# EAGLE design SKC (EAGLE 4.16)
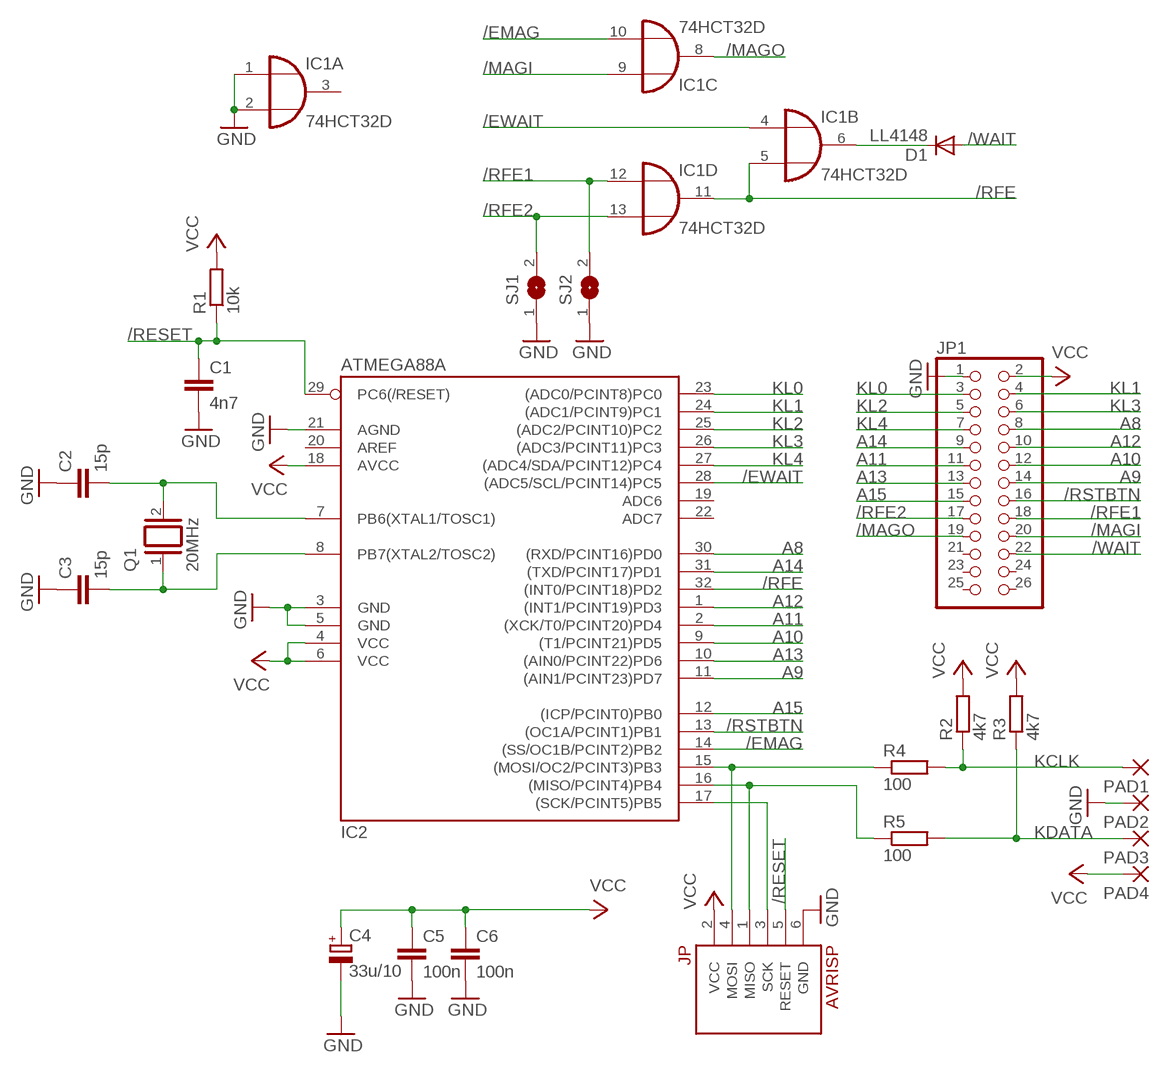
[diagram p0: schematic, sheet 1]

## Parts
C1  4n7  C-EUC0805  [C0805]
C2  15p  C-EUC0805  [C0805]
C3  15p  C-EUC0805  [C0805]
C4  33u/10  CPOL-EUSMCD  [SMC_D]
C5  100n  C-EUC0805  [C0805]
C6  100n  C-EUC0805  [C0805]
D1  LL4148  DIODE-MINIMELF  [MINIMELF]
IC1  74HCT32D  [SO14]
IC2  ATMEGA88A  [TQFP32]
JP  AVRISP  [2X3]
JP1  PINHD-2X13  [2X13]
PAD1  2,54/1,0  [2,54/1,0]
PAD2  2,54/1,0  [2,54/1,0]
PAD3  2,54/1,0  [2,54/1,0]
PAD4  2,54/1,0  [2,54/1,0]
Q1  20MHz  XTAL/S  [QS]
R1  10k  R-EU_R0805  [R0805]
R2  4k7  R-EU_R0805  [R0805]
R3  4k7  R-EU_R0805  [R0805]
R4  100  R-EU_R0805  [R0805]
R5  100  R-EU_R0805  [R0805]
SJ1  SJ  [SJ]
SJ2  SJ  [SJ]

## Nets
/EMAG: IC1.10(C:I1) IC2.14((SS/OC1B/PCINT2)PB2)
/EWAIT: IC1.4(B:I0) IC2.28((ADC5/SCL/PCINT14)PC5)
/MAGI: IC1.9(C:I0) JP1.20
/MAGO: IC1.8(C:O) JP1.19
/RESET: C1.1 IC2.29(PC6(/RESET)) JP.5(RESET) R1.1
/RFE: IC1.5(B:I1) IC1.11(D:O) IC2.32((INT0/PCINT18)PD2)
/RFE1: IC1.12(D:I0) JP1.18 SJ2.2
/RFE2: IC1.13(D:I1) JP1.17 SJ1.2
/RSTBTN: IC2.13((OC1A/PCINT1)PB1) JP1.16
/WAIT: D1.A JP1.22
A8: IC2.30((RXD/PCINT16)PD0) JP1.8
A9: IC2.11((AIN1/PCINT23)PD7) JP1.14
A10: IC2.9((T1/PCINT21)PD5) JP1.12
A11: IC2.2((XCK/T0/PCINT20)PD4) JP1.11
A12: IC2.1((INT1/PCINT19)PD3) JP1.10
A13: IC2.10((AIN0/PCINT22)PD6) JP1.13
A14: IC2.31((TXD/PCINT17)PD1) JP1.9
A15: IC2.12((ICP/PCINT0)PB0) JP1.15
GND: C1.2 C2.1 C3.1 C4.- C5.2 C6.2 IC1.1(A:I0) IC1.2(A:I1) IC2.3(GND) IC2.5(GND) IC2.21(AGND) JP1.1 JP.6(GND) PAD2.1(P) SJ1.1 SJ2.1
KCLK: PAD1.1(P) R2.1 R4.2
KDATA: PAD3.1(P) R3.1 R5.2
KL0: IC2.23((ADC0/PCINT8)PC0) JP1.3
KL1: IC2.24((ADC1/PCINT9)PC1) JP1.4
KL2: IC2.25((ADC2/PCINT10)PC2) JP1.5
KL3: IC2.26((ADC3/PCINT11)PC3) JP1.6
KL4: IC2.27((ADC4/SDA/PCINT12)PC4) JP1.7
N$1: C3.2 IC2.8(PB7(XTAL2/TOSC2)) Q1.1
N$2: C2.2 IC2.7(PB6(XTAL1/TOSC1)) Q1.2
N$3: IC2.15((MOSI/OC2/PCINT3)PB3) JP.4(MOSI) R4.1
N$4: IC2.16((MISO/PCINT4)PB4) JP.1(MISO) R5.1
N$5: IC2.17((SCK/PCINT5)PB5) JP.3(SCK)
N$7: D1.C IC1.6(B:O)
VCC: C4.+ C5.1 C6.1 IC2.4(VCC) IC2.6(VCC) IC2.18(AVCC) JP1.2 JP.2(VCC) PAD4.1(P) R1.2 R2.2 R3.2
Unconnected: IC1.3(A:O) IC2.19(ADC6) IC2.20(AREF) IC2.22(ADC7) JP1.21 JP1.23 JP1.24 JP1.25 JP1.26

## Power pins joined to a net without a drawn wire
GND: IC1.7(P:GND)
VCC: IC1.14(P:VCC)

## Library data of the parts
C1-C3 C5 C6 = rcl:C-EU: CAPACITOR, European symbol
C4 = rcl:CPOL-EU: POLARIZED CAPACITOR, European symbol
D1 = diode:DIODE-: DIODE
IC1 = 74xx-eu:74*32: Quad 2-input OR gate
IC2 = atmega88:ATMEGA88*A
JP = avrprog:AVRISP
JP1 = pinhead:PINHD-2X13: PIN HEADER
PAD1-PAD4 = wirepad:2,54/1,0: THROUGH-HOLE PAD
Q1 = special:XTAL/S: CRYSTAL
R1-R5 = rcl:R-EU_: RESISTOR, European symbol
SJ1 SJ2 = jumper:SJ: SMD solder JUMPER

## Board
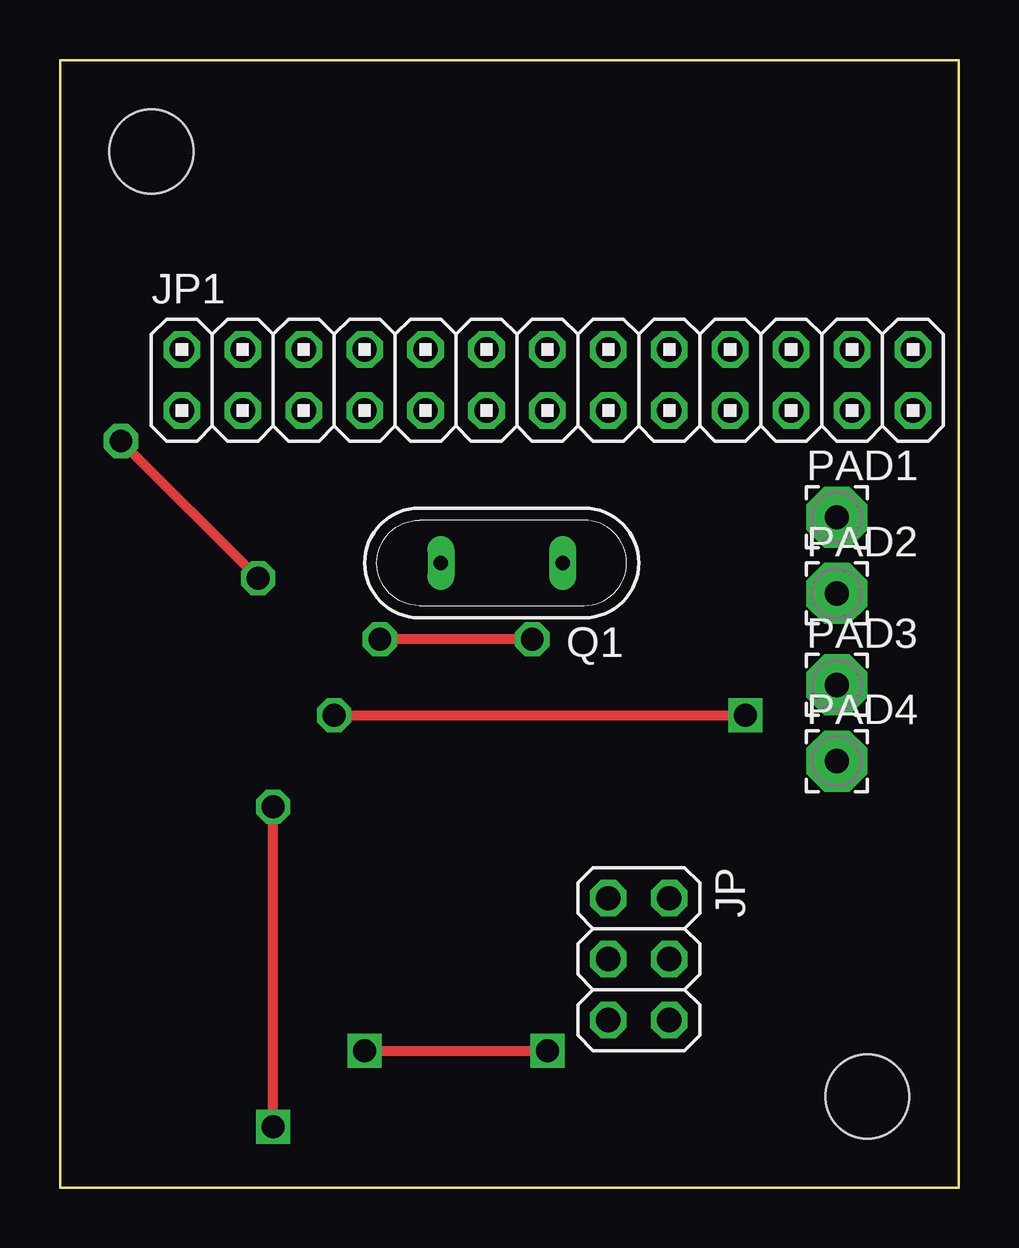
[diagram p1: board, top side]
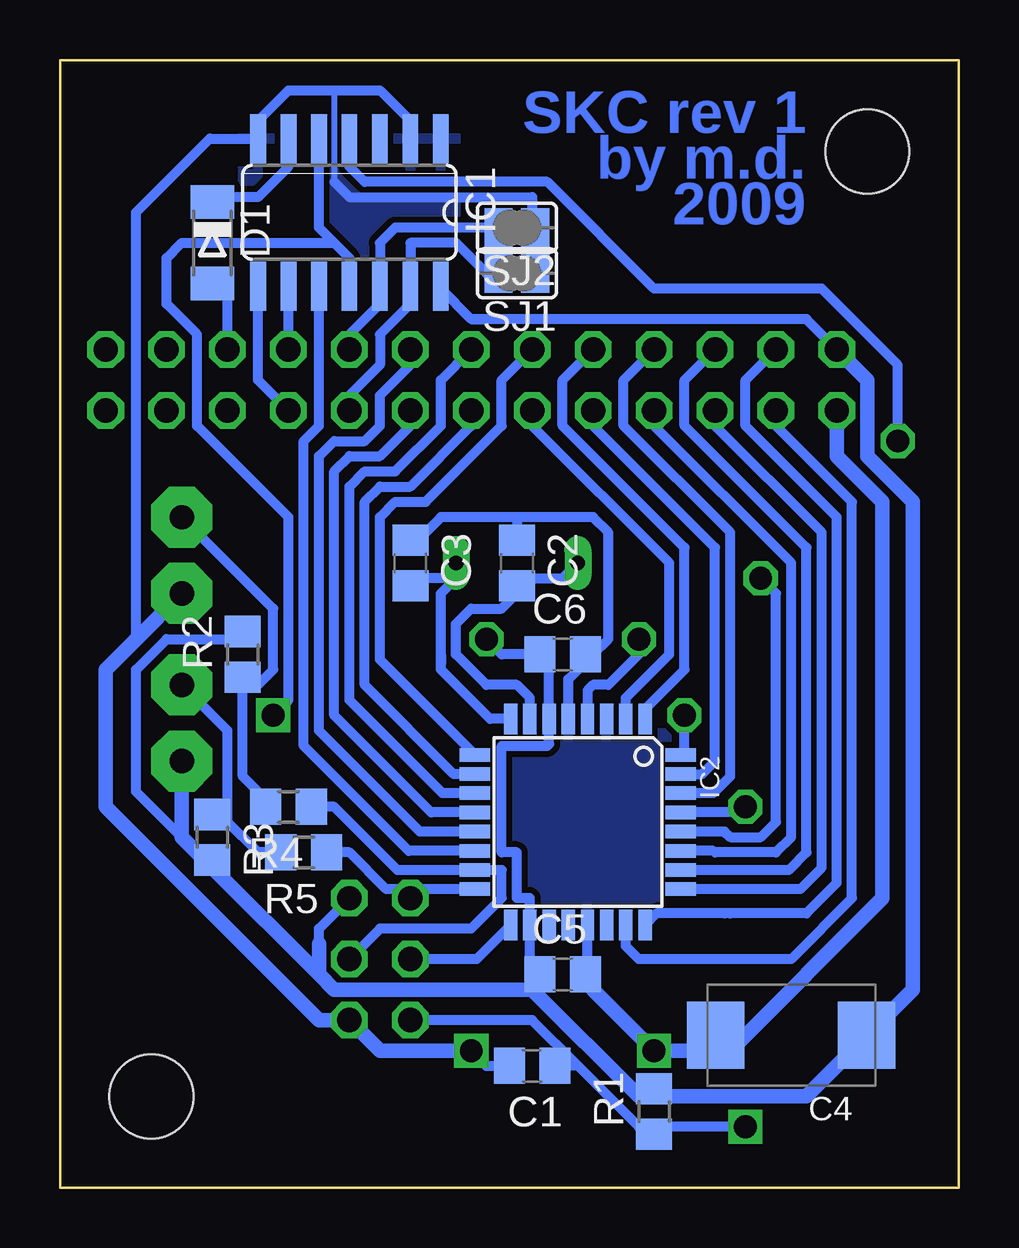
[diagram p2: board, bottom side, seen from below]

Size 37.47 x 46.99 mm. Coordinates in mm from the lower left corner, seen from the top.
Outline: 0,0 0,46.99 37.47,46.99 37.47,0 0,0
Copper layers (1*16): Top 0.035mm / dielectric 1.5mm / Bottom 0.035mm
Design rules "default": minimum track width 10mil, minimum drill 24mil, track to track 8mil, track to pad 7mil, pad to pad 8mil, via to via 8mil, smd to smd 8mil, copper to edge 40mil, drill to drill 8mil, minimum pad ring 10mil, minimum via ring 8mil, stop-mask expansion 4mil, vias tented up to drill 0mil, thermal gap 10mil
Holes 3.5 mm at 33.66,3.81 3.81,43.18

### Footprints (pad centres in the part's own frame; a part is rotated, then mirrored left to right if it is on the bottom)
C0805 = smd 1.3 x 1.5: 1 -0.95,0; 2 0.95,0
SMC_D = smd 2.4 x 2.8: + -3.15,0; - 3.15,0
MINIMELF = smd 1.4 x 1.8: A 1.7,0; C -1.7,0
SO14 = smd 0.66 x 2.032: 1 -3.81,-3.073; 2 -2.54,-3.073; 3 -1.27,-3.073; 4 0,-3.073; 5 1.27,-3.073; 6 2.54,-3.073; 7 3.81,-3.073; 8 3.81,3.073; 9 2.54,3.073; 10 1.27,3.073; 11 0,3.073; 12 -1.27,3.073; 13 -2.54,3.073; 14 -3.81,3.073
TQFP32 = smd 1.27 x 0.559: 1 -4.293,2.8; 2 -4.293,2; 3 -4.293,1.2; 4 -4.293,0.4; 5 -4.293,-0.4; 6 -4.293,-1.2; 7 -4.293,-2; 8 -4.293,-2.8; 17 4.293,-2.8; 18 4.293,-2; 19 4.293,-1.2; 20 4.293,-0.4; 21 4.293,0.4; 22 4.293,1.2; 23 4.293,2; 24 4.293,2.8 | smd 0.559 x 1.27: 9 -2.8,-4.293; 10 -2,-4.293; 11 -1.2,-4.293; 12 -0.4,-4.293; 13 0.4,-4.293; 14 1.2,-4.293; 15 2,-4.293; 16 2.8,-4.293; 25 2.8,4.293; 26 2,4.293; 27 1.2,4.293; 28 0.4,4.293; 29 -0.4,4.293; 30 -1.2,4.293; 31 -2,4.293; 32 -2.8,4.293
2X3 = drill 1.016 octagon: 1 -2.54,-1.27; 2 -2.54,1.27; 3 0,-1.27; 4 0,1.27; 5 2.54,-1.27; 6 2.54,1.27
2X13 = drill 1.016 octagon: 1 -15.24,-1.27; 2 -15.24,1.27; 3 -12.7,-1.27; 4 -12.7,1.27; 5 -10.16,-1.27; 6 -10.16,1.27; 7 -7.62,-1.27; 8 -7.62,1.27; 9 -5.08,-1.27; 10 -5.08,1.27; 11 -2.54,-1.27; 12 -2.54,1.27; 13 0,-1.27; 14 0,1.27; 15 2.54,-1.27; 16 2.54,1.27; 17 5.08,-1.27; 18 5.08,1.27; 19 7.62,-1.27; 20 7.62,1.27; 21 10.16,-1.27; 22 10.16,1.27; 23 12.7,-1.27; 24 12.7,1.27; 25 15.24,-1.27; 26 15.24,1.27
2,54/1,0 = drill 1.016 pad 2.54 octagon: 1 0,0
QS = drill 0.61 long: 1 -2.54,0; 2 2.54,0
R0805 = smd 1.3 x 1.5: 1 -0.95,0; 2 0.95,0
SJ = smd 1.168 x 1.6: 1 -0.762,0; 2 0.762,0

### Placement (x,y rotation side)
C1  17.78,5.08 180 bottom
C2  18.41,26.04 270 bottom
C3  22.86,26.04 270 bottom
C4  6.99,6.35 180 bottom
C5  16.51,8.89 0 bottom
C6  16.51,22.23 0 bottom
D1  31.11,39.37 270 bottom
IC1  25.4,40.64 180 bottom
IC2  15.88,15.24 270 bottom
JP  24.13,9.53 270 top
JP1  20.32,33.66 0 top
PAD1  32.38,27.94 0 top
PAD2  32.38,24.77 0 top
PAD3  32.38,20.95 0 top
PAD4  32.38,17.78 0 top
Q1  18.41,26.04 180 top
R1  12.7,3.17 90 bottom
R2  29.84,22.23 90 bottom
R3  31.11,14.61 270 bottom
R4  27.94,15.88 180 bottom
R5  27.3,13.97 180 bottom
SJ1  18.41,38.1 180 bottom
SJ2  18.41,40.01 180 bottom

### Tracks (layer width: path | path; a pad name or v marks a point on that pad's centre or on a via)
/EMAG
  Bottom 0.406: IC2.14 22.93,14.04 27.3,18.41 27.3,31.11 26.67,31.75 IC1.10
/EWAIT  (via drill 0.95)
  Top 0.406: v8.26,25.4 v2.54,31.11
  Bottom 0.406: IC2.28 9.76,14.84 9.53,14.61 8.26,14.61 7.62,15.24 7.62,24.77 v8.26,25.4 | v2.54,31.11 2.54,34.29 5.71,37.47 12.7,37.47 17.14,41.91 24.77,41.91 25.4,42.55 25.4,43.81 IC1.4
/MAGI
  Bottom 0.406: JP1.20 IC1.9
/MAGO
  Bottom 0.406: IC1.8 29.21,33.66 JP1.19
/RESET  (via drill 0.95)
  Top 0.406: v8.89,2.54 v8.89,15.88
  Bottom 0.254: 12.7,2.54 R1.1
  Bottom 0.406: IC2.29 9.12,15.64 v8.89,15.88 | JP.5 17.78,6.99 15.88,5.08 | 15.88,5.08 13.34,2.54 12.7,2.54 v8.89,2.54 | 15.88,5.08 C1.1
/RFE  (via drill 0.95)
  Top 0.406: v11.43,19.68 v28.57,19.68
  Bottom 0.406: IC2.32 11.43,18.19 v11.43,19.68 | v28.57,19.68 27.94,20.32 27.94,27.94 31.75,31.75 31.75,35.56 33.02,36.83 33.02,38.73 32.38,39.37 26.04,39.37 | IC1.11 25.4,38.73 26.04,39.37 | 26.04,39.37 26.67,40.01 IC1.5 26.67,43.81
/RFE1
  Bottom 0.406: JP1.18 25.4,35.56 24.13,36.83 IC1.12 24.13,39.37 23.5,40.01 SJ2.2 19.05,40.01
/RFE2
  Bottom 0.406: JP1.17 25.4,33.02 24.13,34.29 24.13,35.56 22.86,36.83 IC1.13 22.86,39.37 20.95,39.37 19.68,38.1 SJ1.2 19.05,38.1
/RSTBTN
  Bottom 0.406: IC2.13 22.46,14.84 26.67,19.05 26.67,30.48 26.04,31.11 24.77,31.11 24.13,31.75 24.13,33.02 22.86,34.29 JP1.16
/WAIT
  Bottom 0.406: D1.A 31.11,37.47 30.48,37.47 JP1.22
A8
  Bottom 0.406: IC2.30 10.23,16.44 9.53,17.14 9.53,27.3 13.97,31.75 13.97,33.66 JP1.8
A9
  Bottom 0.406: IC2.11 21.52,16.44 25.4,20.32 25.4,29.21 24.77,29.84 23.5,29.84 21.59,31.75 21.59,33.66 JP1.14
A10
  Bottom 0.406: IC2.9 24.13,22 24.13,27.94 23.5,28.57 22.23,28.57 19.05,31.75 19.05,33.66 JP1.12
A11
  Bottom 0.406: IC2.2 13.88,20.41 12.06,22.23 12.06,26.04 17.78,31.75 JP1.11
A12
  Bottom 0.406: IC2.1 13.07,19.95 11.43,21.59 11.43,26.67 16.51,31.75 16.51,33.66 JP1.10
A13
  Bottom 0.406: IC2.10 21.05,17.24 24.77,20.95 24.77,28.57 24.13,29.21 22.86,29.21 20.32,31.75 JP1.13
A14
  Bottom 0.406: IC2.31 10.7,17.24 10.16,17.78 10.16,26.67 15.24,31.75 JP1.9
A15
  Bottom 0.406: IC2.12 21.99,15.64 26.04,19.68 26.04,29.84 25.4,30.48 24.13,30.48 22.86,31.75 JP1.15
GND  (via drill 0.95)
  Top 0.406: v12.7,5.71 v20.32,5.71
  Bottom 0.254: 26.04,45.72 26.04,41.91
  Bottom 0.406: 18.41,27.94 C2.1 | C3.1 22.55,26.98 21.59,27.94 18.41,27.94 | IC2.5 16.27,21.19 15.24,22.23 | 15.24,22.23 14.61,22.86 14.61,27.3 15.24,27.94 18.41,27.94 | 15.47,9.12 IC2.21 | v20.32,5.71 19.68,5.08 C1.2 | 15.88,22.23 C6.2 15.24,22.23 | C4.- 10.16,6.35 10.16,5.71 9.53,5.71 | 34.29,22.86 34.29,40.64 31.22,43.71 IC1.7 29.21,44.45 27.94,45.72 26.04,45.72 24.13,45.72 22.86,44.45 IC1.2 | 26.04,41.91 25.4,41.27 17.78,41.27 17.78,40.01 | SJ1.1 17.78,38.1 17.78,40.01 | 17.78,40.01 SJ2.1 | IC1.1 21.59,44.45
  Bottom 0.61: v20.32,5.71 24.13,5.71 JP.6 26.67,6.99 35.56,15.88 35.56,21.59 34.29,22.86 PAD2.1 | 10.16,5.71 v12.7,5.71 15.24,8.26 15.24,8.89 | 15.24,8.89 15.47,9.12 | 15.24,8.89 C5.2 | JP1.1 5.08,30.48 3.17,28.57 3.17,12.06 9.53,5.71
  pour Bottom (isolate 0.254): 12.06,11.43 12.06,19.05 19.68,19.05 19.68,11.43
  pour Bottom (isolate 0.254): 20.95,36.83 20.95,44.45 29.84,44.45 29.84,36.83
KCLK
  Bottom 0.406: 29.21,15.88 28.89,16.2 R4.2 29.21,15.88 | 29.21,15.88 29.21,16.51 29.84,17.14 29.84,20.95 | 29.84,20.95 R2.1 | 29.84,20.95 29.21,20.95 28.57,21.59 28.57,24.13 PAD1.1
KDATA
  Bottom 0.406: R5.2 29.21,13.97 30.48,15.24 | 30.48,15.24 30.48,19.05 PAD3.1 | 30.48,15.24 31.11,15.24 R3.1
KL0
  Bottom 0.406: IC2.23 13.88,10.06 13.34,9.53 6.99,9.53 4.45,12.06 4.45,28.57 7.62,31.75 JP1.3
KL1
  Bottom 0.406: 9.53,11.43 9.75,11.43 | 9.53,11.43 6.35,11.43 5.08,12.7 5.08,27.94 8.89,31.75 8.89,33.66 JP1.4 | IC2.24 12.59,11.43 9.53,11.43
KL2
  Bottom 0.406: IC2.25 6.61,12.44 5.71,13.34 5.71,27.3 10.16,31.75 JP1.5
KL3
  Bottom 0.406: IC2.26 7.08,13.24 6.35,13.97 6.35,26.67 11.43,31.75 11.43,33.66 JP1.6
KL4
  Bottom 0.406: IC2.27 10.23,14.04 10.16,13.97 7.62,13.97 6.99,14.61 6.99,26.04 12.7,31.75 JP1.7
N$1
  Bottom 0.406: 21.59,22.23 21.59,21.81 | 21.59,22.23 21.59,21.59 19.53,19.53 IC2.8 | 20.95,25.4 Q1.1 | 20.95,25.4 21.59,24.77 21.59,22.23 | C3.2 22.55,25.4 20.95,25.4
N$2
  Bottom 0.406: IC2.7 17.88,20.41 18.41,20.95 19.68,20.95 20.95,22.23 20.95,23.5 20.32,24.13 19.05,24.13 18.41,24.77 18.41,25.4 | 18.41,25.4 C2.2 | Q1.2 16.51,25.4 18.41,25.4
N$3
  Bottom 0.406: JP.4 24.13,10.79 20.32,10.79 19.05,12.06 19.05,13.24 IC2.15 23.4,13.24 26.04,15.88 R4.1
N$4
  Bottom 0.406: 22.48,12.44 JP.1 | IC2.16 22.48,12.44 | R5.1 25.4,13.97 23.87,12.44 22.48,12.44
N$5
  Bottom 0.406: IC2.17 20.1,9.53 JP.3
N$7
  Bottom 0.406: IC1.6 27.94,42.55 29.21,41.27 31.11,41.27 D1.C
VCC  (via drill 0.95)
  Top 0.406: v19.68,22.86 v13.34,22.86
  Bottom 0.254: 12.7,3.81 R1.2
  Bottom 0.406: JP.2 26.67,10.79 26.67,10.16 | 17.78,8.89 17.88,8.98 IC2.18 17.88,12.06 18.41,12.06 18.41,13.97 19.05,13.97 19.05,18.41 17.14,18.41 17.07,18.48 IC2.6 17.07,22.3 17.14,22.23 C6.1 19.05,22.23 v19.68,22.86 | IC2.4 15.47,20.72 15.24,20.95 14.61,20.95 13.34,22.23 v13.34,22.86 | C4.+ 3.81,6.35 | 20.32,36.2 6.35,36.2 JP1.2 | 20.32,36.2 19.68,36.2 | 20.32,36.2 21.59,37.47 | 21.59,37.47 21.59,36.83 | 21.59,37.47 IC1.14 | R2.2 29.84,22.86 33.02,22.86 34.29,21.59 34.29,16.51 32.38,14.61 | 31.11,13.34 R3.2
  Bottom 0.61: 26.67,8.89 26.67,10.16 | 26.67,8.89 26.04,8.26 17.78,8.26 | JP1.2 3.81,33.66 3.81,30.48 1.91,28.57 1.91,8.26 3.81,6.35 6.35,3.81 12.7,3.81 13.34,3.81 17.78,8.26 | 26.67,8.89 31.11,13.34 32.38,14.61 PAD4.1 | C5.1 17.78,8.89 17.78,8.26

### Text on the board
Bottom: SKC rev 1 | by m.d. | 2009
